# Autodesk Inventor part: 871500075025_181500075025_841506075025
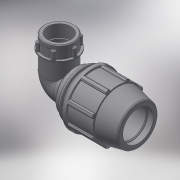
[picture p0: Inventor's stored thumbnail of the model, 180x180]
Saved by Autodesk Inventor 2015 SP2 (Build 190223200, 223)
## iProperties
Created: 2017-02
Part Number: 871500075025_181500075025_841506075025
Material: Generic
Description: PLASSON 90° ELBOW FEMALE ADAPTOR 75-2.1/2"
Document SubType Name: Modeling
Designer: KIM
Mass: 1287.77 g
Surface Area: 1760.4 cm^2
Volume: 1287.77 cm^3
Density: 1 g/cm^3
Appearance: Default
Author: KIM
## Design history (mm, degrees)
derived "87150.ipt"
feature "Solid1::87150.ipt"
tag "TaggingFeature1"
body "Solid1"
other parameters: "d2" = 75, "d4" = 16.33333, "d5" = 49, "d7" = 132, "d9" = 28, "d11" = 6.53333, "d13" = 120 deg, "d14" = 97.5, "d15" = 12 deg, "d16" = 114.84, "d18" = 3.75, "d19" = 35 deg, "d20" = 17.5 deg, "d21" = 122.76, "d23" = 0, "d25" = 360 deg, "d27" = 2.64, "d33" = 1.5, "d42" = 72.52, "d43" = 3.96, "d46" = 2.25, "d51" = 196, "d68" = 13.06667, "d72" = 105, "d73" = 93.8938, "d74" = 36, "d75" = 107.97787, "d76" = 72.226, "d77" = 39.6, "d79" = 28.8904, "d80" = 2.16678, "d83" = 0, "d84" = 0, "d91" = 99, "d93" = 137, "d94" = 72.226, "d95" = 50.5582, "d96" = 13.06667, "d97" = 50 deg, "d98" = 65.0034, "d99" = 0.5, "d100" = 0.5, "d101" = 12, "d102" = 93.8938, "d103" = 30.96, "d104" = 0, "d108" = 360 deg, "d110" = 2.81681, "d111" = 8.8, "d112" = 0, "d113" = 3.26667, "d114" = 3.26667, "d115" = 111.3948, "d_" = 75, "E_" = 132, "A_" = 196, "l_" = 137, "l_2" = 36, "A_1" = 105, "Rp_" = 72.226, "d105" = 14.08407
